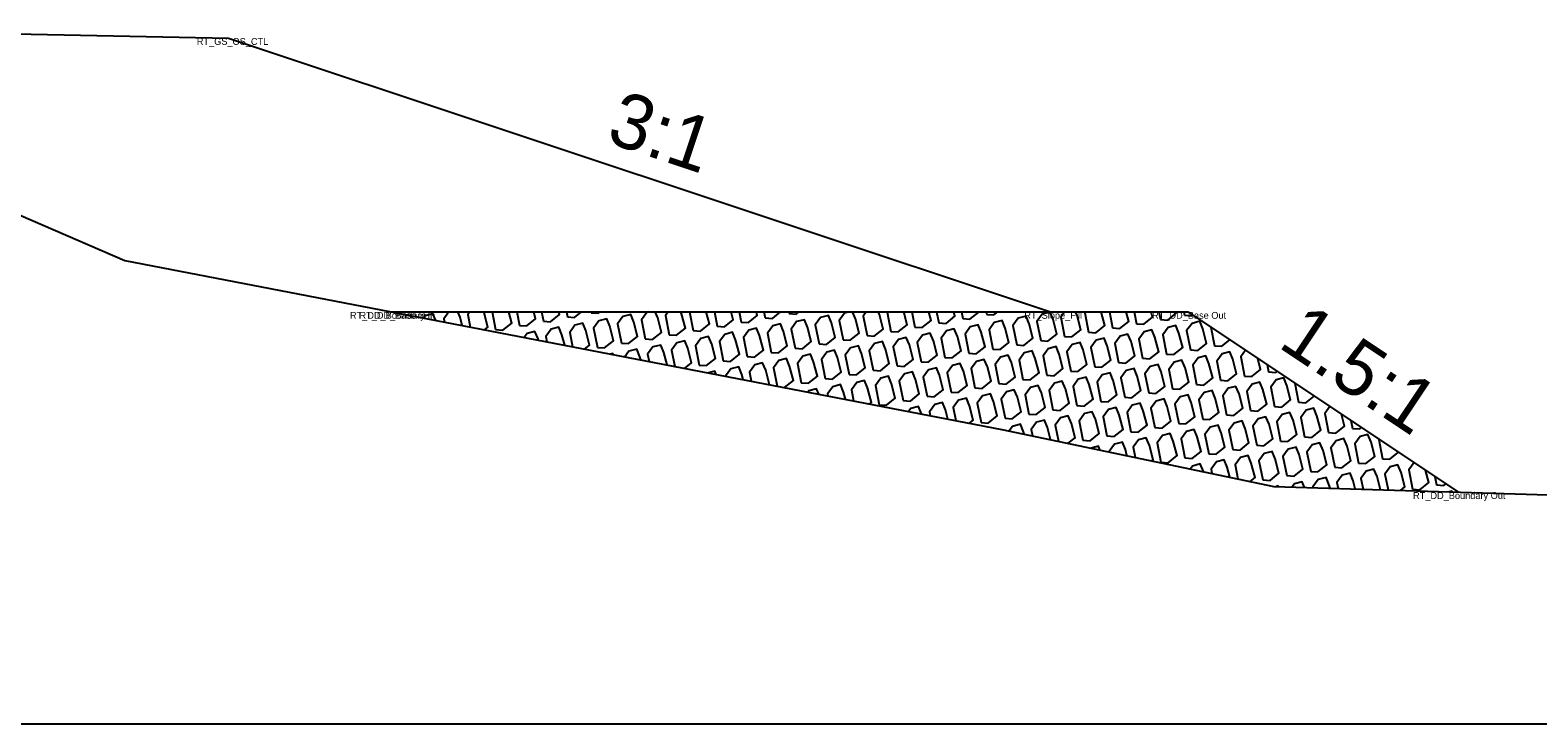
# Model space of a CAD drawing. Extents: x -26 to 203, y -10 to 20020.
# Drawn here: x 117.11 to 139.06, y 4000 to 4010.1 of the extents above; entities that cross this region are included whole.
import ezdxf

# ---------------------------------------------------------------- set-up
doc = ezdxf.new("R2010")
doc.units = 0
for name, color, linetype in [('Default', 7, 'Continuous'), ('Exist Cross Section Cell', 7, 'Continuous'), ('Exist XS Ground Line', 7, 'Continuous'), ('Old_Level_1', 7, 'Continuous'), ('Prop CMT Rip Rap Class II', 7, 'Continuous'), ('Prop CMT Slope Grass', 7, 'Continuous'), ('Prop XS Side Slope Text', 7, 'Continuous')]:
    doc.layers.add(name, color=color, linetype=linetype)

msp = doc.modelspace()

# ---------------------------------------------------------------- linework, layer by layer
at = {"layer": 'Exist Cross Section Cell'}
msp.add_line((100, 4000), (200, 4000), dxfattribs=at)
at = {"layer": 'Exist XS Ground Line'}
for p, q in [((116.426, 4007.643), (118.492, 4006.747)), ((118.492, 4006.747), (131.26, 4004.288)), ((131.26, 4004.288), (135.219, 4003.459)), ((135.219, 4003.459), (139.534, 4003.324))]:
    msp.add_line(p, q, dxfattribs=at)
at = {"layer": 'Old_Level_1'}
for p, q in [((123.838, 4006), (123.889, 4005.742)), ((124.198, 4006), (124.237, 4005.803)), ((124.559, 4006), (124.586, 4005.865)), ((124.92, 4006), (124.935, 4005.926)), ((125.281, 4006), (125.283, 4005.988)), ((126.713, 4006), (126.766, 4005.73)), ((127.074, 4006), (127.115, 4005.791)), ((127.434, 4006), (127.464, 4005.853)), ((127.795, 4006), (127.812, 4005.914)), ((128.156, 4006), (128.161, 4005.976)), ((129.949, 4006), (129.993, 4005.779)), ((130.31, 4006), (130.341, 4005.84)), ((130.67, 4006), (130.69, 4005.902)), ((131.031, 4006), (131.039, 4005.963)), ((132.824, 4006), (132.87, 4005.766)), ((133.185, 4006), (133.219, 4005.828)), ((133.546, 4006), (133.568, 4005.889)), ((133.906, 4006), (133.916, 4005.951)), ((134.3, 4005.779), (134.354, 4005.508)), ((135.119, 4005.233), (135.14, 4005.127)), ((135.522, 4004.964), (135.577, 4004.685)), ((136.34, 4004.419), (136.363, 4004.303)), ((137.562, 4003.604), (137.587, 4003.48))]:
    msp.add_line(p, q, dxfattribs=at)
for points in [[(122.408, 4006), (122.511, 4005.993), (122.52, 4006)], [(123.019, 4005.875), (122.978, 4005.973), (122.864, 4005.944), (122.84, 4005.909)], [(123.209, 4006), (123.136, 4005.899), (123.146, 4005.851)], [(123.404, 4005.801), (123.372, 4005.925), (123.341, 4006)], [(123.513, 4006), (123.485, 4005.961), (123.521, 4005.778)], [(123.728, 4005.738), (123.775, 4005.776), (123.721, 4005.987), (123.715, 4006)], [(123.889, 4005.742), (123.994, 4005.734), (124.124, 4005.838), (124.082, 4006)], [(124.237, 4005.803), (124.343, 4005.796), (124.472, 4005.899), (124.446, 4006)], [(124.586, 4005.865), (124.691, 4005.857), (124.821, 4005.96), (124.811, 4006)], [(124.935, 4005.926), (125.04, 4005.919), (125.142, 4006)], [(125.183, 4005.458), (125.258, 4005.518), (125.204, 4005.728), (125.159, 4005.838), (125.045, 4005.809), (124.968, 4005.702), (125.01, 4005.492)], [(125.283, 4005.988), (125.388, 4005.98), (125.413, 4006)], [(125.372, 4005.484), (125.477, 4005.476), (125.607, 4005.579), (125.552, 4005.79), (125.507, 4005.9), (125.394, 4005.87), (125.316, 4005.764), (125.372, 4005.484)], [(126.117, 4006), (126.091, 4005.993), (126.014, 4005.887), (126.069, 4005.607)], [(126.069, 4005.607), (126.175, 4005.599), (126.304, 4005.702), (126.25, 4005.913), (126.214, 4006)], [(126.4, 4006), (126.362, 4005.948), (126.418, 4005.668)], [(126.418, 4005.668), (126.523, 4005.661), (126.653, 4005.764), (126.598, 4005.974), (126.588, 4006)], [(126.766, 4005.73), (126.872, 4005.722), (127.001, 4005.825), (126.956, 4006)], [(127.115, 4005.791), (127.22, 4005.783), (127.35, 4005.887), (127.321, 4006)], [(127.464, 4005.853), (127.569, 4005.845), (127.698, 4005.948), (127.685, 4006)], [(127.812, 4005.914), (127.918, 4005.906), (128.035, 4006)], [(128.161, 4005.976), (128.266, 4005.968), (128.306, 4006)], [(129.043, 4006), (128.968, 4005.981), (128.891, 4005.874), (128.947, 4005.594)], [(128.947, 4005.594), (129.052, 4005.587), (129.182, 4005.69), (129.127, 4005.901), (129.086, 4006)], [(129.286, 4006), (129.24, 4005.936), (129.296, 4005.656)], [(129.296, 4005.656), (129.401, 4005.648), (129.53, 4005.751), (129.476, 4005.962), (129.46, 4006)], [(129.59, 4006), (129.589, 4005.997), (129.644, 4005.717)], [(129.644, 4005.717), (129.749, 4005.71), (129.879, 4005.813), (129.831, 4006)], [(129.993, 4005.779), (130.098, 4005.771), (130.228, 4005.874), (130.195, 4006)], [(130.341, 4005.84), (130.447, 4005.833), (130.576, 4005.936), (130.56, 4006)], [(130.69, 4005.902), (130.795, 4005.894), (130.925, 4005.997), (130.924, 4006)], [(131.039, 4005.963), (131.144, 4005.956), (131.2, 4006)], [(132.173, 4006), (132.118, 4005.924), (132.173, 4005.644)], [(132.173, 4005.644), (132.278, 4005.636), (132.408, 4005.739), (132.354, 4005.95), (132.333, 4006)], [(132.477, 4006), (132.466, 4005.985), (132.522, 4005.705)], [(132.522, 4005.705), (132.627, 4005.697), (132.757, 4005.801), (132.705, 4006)], [(132.87, 4005.766), (132.976, 4005.759), (133.105, 4005.862), (133.07, 4006)], [(133.219, 4005.828), (133.324, 4005.82), (133.454, 4005.923), (133.434, 4006)], [(133.568, 4005.889), (133.673, 4005.882), (133.802, 4005.985), (133.798, 4006)], [(133.916, 4005.951), (134.021, 4005.943), (134.036, 4005.955)], [(124.511, 4005.588), (124.507, 4005.606), (124.462, 4005.715), (124.348, 4005.686), (124.305, 4005.627)], [(124.895, 4005.514), (124.855, 4005.667), (124.81, 4005.777), (124.696, 4005.747), (124.619, 4005.641), (124.635, 4005.564)], [(132.611, 4005.201), (132.716, 4005.193), (132.845, 4005.296), (132.791, 4005.507), (132.746, 4005.617), (132.632, 4005.587), (132.555, 4005.481), (132.611, 4005.201)], [(132.959, 4005.262), (133.065, 4005.255), (133.194, 4005.358), (133.14, 4005.569), (133.094, 4005.678), (132.981, 4005.649), (132.904, 4005.542), (132.959, 4005.262)], [(133.308, 4005.324), (133.413, 4005.316), (133.543, 4005.419), (133.488, 4005.63), (133.443, 4005.74), (133.329, 4005.71), (133.252, 4005.604), (133.308, 4005.324)], [(134.354, 4005.508), (134.459, 4005.501), (134.577, 4005.594)], [(125.604, 4005.377), (125.596, 4005.396), (125.559, 4005.386)], [(126.002, 4005.301), (125.99, 4005.347), (125.945, 4005.457), (125.831, 4005.428), (125.771, 4005.345)], [(126.386, 4005.227), (126.339, 4005.409), (126.293, 4005.518), (126.18, 4005.489), (126.103, 4005.383), (126.123, 4005.277)], [(126.639, 4005.178), (126.742, 4005.26), (126.687, 4005.47), (126.642, 4005.58), (126.528, 4005.551), (126.451, 4005.444), (126.499, 4005.205)], [(134.805, 4005.442), (134.736, 4005.346), (134.791, 4005.066)], [(127.493, 4005.014), (127.473, 4005.089), (127.428, 4005.199), (127.314, 4005.169), (127.237, 4005.063), (127.237, 4005.063)], [(127.876, 4004.94), (127.876, 4004.94), (127.822, 4005.151), (127.777, 4005.26), (127.663, 4005.231), (127.586, 4005.124), (127.612, 4004.991)], [(128.09, 4004.899), (128.095, 4004.898), (128.225, 4005.001), (128.17, 4005.212), (128.125, 4005.322), (128.011, 4005.292), (127.934, 4005.186), (127.988, 4004.918)], [(134.791, 4005.066), (134.896, 4005.058), (135.026, 4005.161), (134.984, 4005.323)], [(127.099, 4005.089), (127.079, 4005.137), (126.982, 4005.112)], [(128.983, 4004.727), (128.956, 4004.831), (128.911, 4004.941), (128.798, 4004.911), (128.72, 4004.805), (128.726, 4004.776)], [(129.332, 4004.66), (129.36, 4004.682), (129.305, 4004.892), (129.26, 4005.002), (129.146, 4004.973), (129.069, 4004.866), (129.101, 4004.704)], [(129.473, 4004.648), (129.579, 4004.64), (129.708, 4004.743), (129.654, 4004.954), (129.609, 4005.064), (129.495, 4005.034), (129.418, 4004.928), (129.473, 4004.648)], [(131.654, 4004.512), (131.759, 4004.505), (131.889, 4004.608), (131.834, 4004.819), (131.789, 4004.928), (131.675, 4004.899), (131.598, 4004.792), (131.654, 4004.512)], [(132.002, 4004.574), (132.108, 4004.566), (132.237, 4004.669), (132.183, 4004.88), (132.138, 4004.99), (132.024, 4004.96), (131.947, 4004.854), (132.002, 4004.574)], [(132.351, 4004.635), (132.456, 4004.628), (132.586, 4004.731), (132.531, 4004.942), (132.486, 4005.051), (132.372, 4005.022), (132.295, 4004.915), (132.351, 4004.635)], [(135.14, 4005.127), (135.245, 4005.119), (135.265, 4005.135)], [(128.595, 4004.801), (128.563, 4004.879), (128.449, 4004.85), (128.436, 4004.832)], [(130.787, 4004.379), (130.843, 4004.424), (130.788, 4004.634), (130.743, 4004.744), (130.629, 4004.714), (130.552, 4004.608), (130.59, 4004.417)], [(135.577, 4004.685), (135.682, 4004.677), (135.806, 4004.775)], [(130.09, 4004.514), (130.046, 4004.621), (129.932, 4004.592), (129.902, 4004.55)], [(130.474, 4004.44), (130.44, 4004.573), (130.395, 4004.682), (130.281, 4004.653), (130.204, 4004.547), (130.215, 4004.49)], [(132.226, 4004.086), (132.326, 4004.165), (132.272, 4004.376), (132.226, 4004.486), (132.113, 4004.456), (132.036, 4004.35), (132.082, 4004.116)], [(136.033, 4004.624), (135.959, 4004.522), (136.015, 4004.242)], [(136.015, 4004.242), (136.12, 4004.234), (136.249, 4004.337), (136.205, 4004.509)], [(131.583, 4004.221), (131.574, 4004.253), (131.529, 4004.363), (131.415, 4004.333), (131.367, 4004.266)], [(131.968, 4004.14), (131.923, 4004.315), (131.878, 4004.424), (131.764, 4004.395), (131.687, 4004.288), (131.706, 4004.195)], [(136.363, 4004.303), (136.469, 4004.296), (136.494, 4004.316)], [(133.08, 4003.907), (133.058, 4003.995), (133.013, 4004.105), (132.899, 4004.075), (132.822, 4003.969), (132.823, 4003.961)], [(133.443, 4003.831), (133.461, 4003.846), (133.406, 4004.056), (133.361, 4004.166), (133.247, 4004.137), (133.17, 4004.03), (133.2, 4003.882)], [(133.575, 4003.812), (133.68, 4003.804), (133.809, 4003.907), (133.755, 4004.118), (133.71, 4004.227), (133.596, 4004.198), (133.519, 4004.092), (133.575, 4003.812)], [(136.749, 4004.146), (136.745, 4004.141), (136.801, 4003.861)], [(132.686, 4003.99), (132.664, 4004.043), (132.56, 4004.016)], [(134.578, 4003.593), (134.541, 4003.737), (134.496, 4003.846), (134.382, 4003.817), (134.305, 4003.711), (134.317, 4003.648)], [(134.874, 4003.532), (134.944, 4003.588), (134.89, 4003.798), (134.844, 4003.908), (134.731, 4003.878), (134.654, 4003.772), (134.694, 4003.569)], [(135.058, 4003.553), (135.163, 4003.546), (135.293, 4003.649), (135.238, 4003.86), (135.193, 4003.969), (135.079, 4003.94), (135.002, 4003.833), (135.058, 4003.553)], [(136.801, 4003.861), (136.906, 4003.853), (137.035, 4003.956)], [(134.193, 4003.674), (134.192, 4003.675), (134.147, 4003.785), (134.033, 4003.755), (134.003, 4003.714)], [(136.403, 4003.422), (136.373, 4003.54), (136.328, 4003.65), (136.214, 4003.62), (136.137, 4003.514), (136.154, 4003.43)], [(136.771, 4003.41), (136.721, 4003.601), (136.676, 4003.711), (136.562, 4003.682), (136.485, 4003.575), (136.517, 4003.418)], [(137.06, 4003.401), (137.124, 4003.452), (137.07, 4003.663), (137.025, 4003.773), (136.911, 4003.743), (136.834, 4003.637), (136.88, 4003.407)], [(137.261, 4003.805), (137.26, 4003.805), (137.183, 4003.698), (137.238, 4003.418)], [(137.238, 4003.418), (137.343, 4003.411), (137.473, 4003.514), (137.426, 4003.695)], [(135.285, 4003.457), (135.282, 4003.465), (135.254, 4003.458)], [(135.664, 4003.445), (135.63, 4003.527), (135.517, 4003.497), (135.483, 4003.451)], [(136.036, 4003.434), (136.024, 4003.478), (135.979, 4003.588), (135.865, 4003.559), (135.788, 4003.452), (135.79, 4003.441)], [(137.587, 4003.48), (137.692, 4003.472), (137.723, 4003.497)], [(137.817, 4003.378), (137.811, 4003.391), (137.764, 4003.379)]]:
    msp.add_lwpolyline(points, dxfattribs=at)
for points in [[(125.721, 4005.545), (125.826, 4005.538), (125.955, 4005.641), (125.901, 4005.851), (125.856, 4005.961), (125.742, 4005.932), (125.665, 4005.825)], [(127.901, 4005.41), (128.006, 4005.402), (128.136, 4005.506), (128.082, 4005.716), (128.036, 4005.826), (127.923, 4005.796), (127.846, 4005.69)], [(128.25, 4005.471), (128.355, 4005.464), (128.485, 4005.567), (128.43, 4005.778), (128.385, 4005.887), (128.271, 4005.858), (128.194, 4005.751)], [(128.598, 4005.533), (128.704, 4005.525), (128.833, 4005.628), (128.779, 4005.839), (128.734, 4005.949), (128.62, 4005.919), (128.543, 4005.813)], [(130.779, 4005.398), (130.884, 4005.39), (131.014, 4005.493), (130.959, 4005.704), (130.914, 4005.813), (130.8, 4005.784), (130.723, 4005.678)], [(131.127, 4005.459), (131.233, 4005.451), (131.362, 4005.555), (131.308, 4005.765), (131.263, 4005.875), (131.149, 4005.846), (131.072, 4005.739)], [(131.476, 4005.521), (131.581, 4005.513), (131.711, 4005.616), (131.656, 4005.827), (131.611, 4005.936), (131.497, 4005.907), (131.42, 4005.801)], [(131.825, 4005.582), (131.93, 4005.574), (132.059, 4005.678), (132.005, 4005.888), (131.96, 4005.998), (131.846, 4005.968), (131.769, 4005.862)], [(134.005, 4005.447), (134.11, 4005.439), (134.24, 4005.542), (134.185, 4005.753), (134.14, 4005.863), (134.027, 4005.833), (133.949, 4005.727)], [(126.855, 4005.226), (126.961, 4005.218), (127.09, 4005.321), (127.036, 4005.532), (126.991, 4005.641), (126.877, 4005.612), (126.8, 4005.506)], [(127.204, 4005.287), (127.309, 4005.279), (127.439, 4005.383), (127.384, 4005.593), (127.339, 4005.703), (127.225, 4005.673), (127.148, 4005.567)], [(127.553, 4005.349), (127.658, 4005.341), (127.787, 4005.444), (127.733, 4005.655), (127.688, 4005.764), (127.574, 4005.735), (127.497, 4005.629)], [(129.733, 4005.213), (129.838, 4005.206), (129.968, 4005.309), (129.913, 4005.519), (129.868, 4005.629), (129.754, 4005.6), (129.677, 4005.493)], [(130.082, 4005.275), (130.187, 4005.267), (130.316, 4005.37), (130.262, 4005.581), (130.217, 4005.691), (130.103, 4005.661), (130.026, 4005.555)], [(130.43, 4005.336), (130.535, 4005.329), (130.665, 4005.432), (130.611, 4005.642), (130.565, 4005.752), (130.452, 4005.723), (130.375, 4005.616)], [(133.656, 4005.385), (133.762, 4005.378), (133.891, 4005.481), (133.837, 4005.691), (133.792, 4005.801), (133.678, 4005.772), (133.601, 4005.665)], [(128.339, 4004.967), (128.444, 4004.96), (128.573, 4005.063), (128.519, 4005.274), (128.474, 4005.383), (128.36, 4005.354), (128.283, 4005.247)], [(128.687, 4005.029), (128.792, 4005.021), (128.922, 4005.124), (128.868, 4005.335), (128.822, 4005.445), (128.709, 4005.415), (128.632, 4005.309)], [(129.036, 4005.09), (129.141, 4005.083), (129.271, 4005.186), (129.216, 4005.396), (129.171, 4005.506), (129.057, 4005.477), (128.98, 4005.37)], [(129.384, 4005.152), (129.49, 4005.144), (129.619, 4005.247), (129.565, 4005.458), (129.52, 4005.568), (129.406, 4005.538), (129.329, 4005.432)], [(131.216, 4004.955), (131.322, 4004.947), (131.451, 4005.051), (131.397, 4005.261), (131.351, 4005.371), (131.238, 4005.341), (131.161, 4005.235)], [(131.565, 4005.017), (131.67, 4005.009), (131.8, 4005.112), (131.745, 4005.323), (131.7, 4005.432), (131.586, 4005.403), (131.509, 4005.297)], [(131.913, 4005.078), (132.019, 4005.07), (132.148, 4005.174), (132.094, 4005.384), (132.049, 4005.494), (131.935, 4005.464), (131.858, 4005.358)], [(132.262, 4005.139), (132.367, 4005.132), (132.497, 4005.235), (132.442, 4005.446), (132.397, 4005.555), (132.284, 4005.526), (132.206, 4005.419)], [(134.443, 4005.004), (134.548, 4004.997), (134.677, 4005.1), (134.623, 4005.31), (134.578, 4005.42), (134.464, 4005.391), (134.387, 4005.284)], [(130.17, 4004.771), (130.276, 4004.763), (130.405, 4004.866), (130.351, 4005.077), (130.306, 4005.186), (130.192, 4005.157), (130.115, 4005.051)], [(130.519, 4004.832), (130.624, 4004.824), (130.754, 4004.928), (130.699, 4005.138), (130.654, 4005.248), (130.541, 4005.219), (130.463, 4005.112)], [(130.868, 4004.894), (130.973, 4004.886), (131.102, 4004.989), (131.048, 4005.2), (131.003, 4005.309), (130.889, 4005.28), (130.812, 4005.174)], [(133.048, 4004.758), (133.153, 4004.751), (133.283, 4004.854), (133.229, 4005.064), (133.183, 4005.174), (133.07, 4005.145), (132.993, 4005.038)], [(133.397, 4004.82), (133.502, 4004.812), (133.632, 4004.915), (133.577, 4005.126), (133.532, 4005.236), (133.418, 4005.206), (133.341, 4005.1)], [(133.745, 4004.881), (133.851, 4004.874), (133.98, 4004.977), (133.926, 4005.187), (133.881, 4005.297), (133.767, 4005.268), (133.69, 4005.161)], [(134.094, 4004.943), (134.199, 4004.935), (134.329, 4005.038), (134.274, 4005.249), (134.229, 4005.359), (134.115, 4005.329), (134.038, 4005.223)], [(129.822, 4004.709), (129.927, 4004.702), (130.057, 4004.805), (130.002, 4005.015), (129.957, 4005.125), (129.843, 4005.096), (129.766, 4004.989)], [(132.7, 4004.697), (132.805, 4004.689), (132.934, 4004.792), (132.88, 4005.003), (132.835, 4005.113), (132.721, 4005.083), (132.644, 4004.977)], [(134.88, 4004.562), (134.985, 4004.554), (135.115, 4004.657), (135.06, 4004.868), (135.015, 4004.977), (134.901, 4004.948), (134.824, 4004.842)], [(135.229, 4004.623), (135.334, 4004.615), (135.463, 4004.719), (135.409, 4004.929), (135.364, 4005.039), (135.25, 4005.009), (135.173, 4004.903)], [(130.957, 4004.39), (131.062, 4004.382), (131.191, 4004.485), (131.137, 4004.696), (131.092, 4004.805), (130.978, 4004.776), (130.901, 4004.67)], [(131.305, 4004.451), (131.41, 4004.443), (131.54, 4004.547), (131.486, 4004.757), (131.44, 4004.867), (131.327, 4004.837), (131.25, 4004.731)], [(133.486, 4004.316), (133.591, 4004.308), (133.72, 4004.411), (133.666, 4004.622), (133.621, 4004.732), (133.507, 4004.702), (133.43, 4004.596)], [(133.834, 4004.377), (133.939, 4004.37), (134.069, 4004.473), (134.015, 4004.683), (133.969, 4004.793), (133.856, 4004.764), (133.779, 4004.657)], [(134.183, 4004.439), (134.288, 4004.431), (134.418, 4004.534), (134.363, 4004.745), (134.318, 4004.854), (134.204, 4004.825), (134.127, 4004.719)], [(134.531, 4004.5), (134.637, 4004.492), (134.766, 4004.596), (134.712, 4004.806), (134.667, 4004.916), (134.553, 4004.887), (134.476, 4004.78)], [(132.44, 4004.131), (132.545, 4004.124), (132.675, 4004.227), (132.62, 4004.437), (132.575, 4004.547), (132.461, 4004.518), (132.384, 4004.411)], [(132.788, 4004.193), (132.894, 4004.185), (133.023, 4004.288), (132.969, 4004.499), (132.924, 4004.609), (132.81, 4004.579), (132.733, 4004.473)], [(133.137, 4004.254), (133.242, 4004.247), (133.372, 4004.35), (133.317, 4004.56), (133.272, 4004.67), (133.158, 4004.641), (133.081, 4004.534)], [(135.317, 4004.119), (135.423, 4004.111), (135.552, 4004.215), (135.498, 4004.425), (135.453, 4004.535), (135.339, 4004.505), (135.262, 4004.399)], [(135.666, 4004.18), (135.771, 4004.173), (135.901, 4004.276), (135.846, 4004.487), (135.801, 4004.596), (135.688, 4004.567), (135.61, 4004.46)], [(133.923, 4003.873), (134.028, 4003.865), (134.158, 4003.969), (134.103, 4004.179), (134.058, 4004.289), (133.945, 4004.26), (133.867, 4004.153)], [(134.272, 4003.935), (134.377, 4003.927), (134.507, 4004.03), (134.452, 4004.241), (134.407, 4004.35), (134.293, 4004.321), (134.216, 4004.215)], [(134.62, 4003.996), (134.726, 4003.988), (134.855, 4004.092), (134.801, 4004.302), (134.756, 4004.412), (134.642, 4004.382), (134.565, 4004.276)], [(134.969, 4004.058), (135.074, 4004.05), (135.204, 4004.153), (135.149, 4004.364), (135.104, 4004.473), (134.99, 4004.444), (134.913, 4004.338)], [(135.755, 4003.676), (135.86, 4003.669), (135.99, 4003.772), (135.935, 4003.983), (135.89, 4004.092), (135.776, 4004.063), (135.699, 4003.956)], [(136.104, 4003.738), (136.209, 4003.73), (136.338, 4003.833), (136.284, 4004.044), (136.239, 4004.154), (136.125, 4004.124), (136.048, 4004.018)], [(136.452, 4003.799), (136.557, 4003.792), (136.687, 4003.895), (136.633, 4004.105), (136.587, 4004.215), (136.474, 4004.186), (136.397, 4004.079)], [(135.406, 4003.615), (135.512, 4003.607), (135.641, 4003.71), (135.587, 4003.921), (135.542, 4004.031), (135.428, 4004.001), (135.351, 4003.895)]]:
    msp.add_lwpolyline(points, close=True, dxfattribs=at)
at = {"layer": 'Prop CMT Rip Rap Class II'}
for points in [[(122.369, 4006), (122.369, 4006)], [(122.369, 4006), (133.968, 4006), (137.906, 4003.375)]]:
    msp.add_lwpolyline(points, dxfattribs=at)
at = {"layer": 'Prop CMT Slope Grass'}
for points in [[(114.25, 4010.104), (120, 4009.989)], [(120, 4009.989), (131.968, 4006)]]:
    msp.add_lwpolyline(points, dxfattribs=at)

# ---------------------------------------------------------------- texts
at = {"layer": 'Default'}
for s, p in [('RT_GS_OS_CTL', (119.54, 4009.889)), ('RT_DD_Boundary In', (121.769, 4005.9)), ('RT_DD_Base In', (121.908, 4005.9)), ('RT_Slope_Fill', (131.586, 4005.9)), ('RT_DD_Base Out', (133.446, 4005.9)), ('RT_DD_Boundary Out', (137.245, 4003.275))]:
    msp.add_text(s, height=0.1, dxfattribs=at).set_placement(p)
at = {"layer": 'Prop XS Side Slope Text'}
for s, rotation, p in [('3:1', 341.5668, (125.478, 4008.48)), ('1.5:1', 326.3086, (135.261, 4005.499))]:
    msp.add_text(s, height=0.8, rotation=rotation, dxfattribs=at).set_placement(p)

doc.saveas('drawing.dxf')
